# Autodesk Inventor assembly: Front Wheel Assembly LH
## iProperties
Length Units: 11269
Angle Units: 11279
Time Units: 11290
Mass Units: 11283
Shininess: 3
Angle Display Precision: 2
Document Length Units: 11269
Document Angle Units: 11279
Document Time Units: 11290
Document Mass Units: 11283
Document Length Units Precision: 3
Document Angle Units Precision: 2
Compacted: True
Created: 2001-08
Part Number: Front Wheel Assembly LH
Document SubType Name: Assembly
Designer: Martin Budgell
Density: 0.0
Volumn: 0.0
Area: 0.0
PropertySet Name: Model Information
Control State: 0
Master: False
Checked Out: False
Author: Martin Budgell
